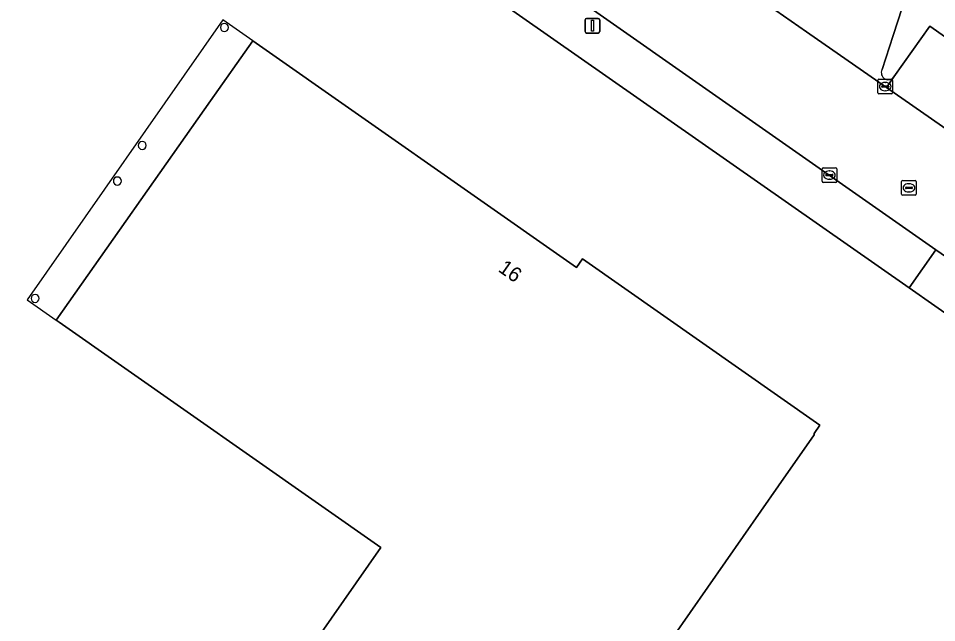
# Model space of a CAD drawing. Extents: x 155018 to 156648, y 383979 to 385733.
# Drawn here: x 155319.4 to 155382, y 385033.8 to 385075 of the extents above; entities that cross this region are included whole.
import ezdxf

# ---------------------------------------------------------------- set-up
doc = ezdxf.new("R2010")
doc.units = 0
for name, color, linetype in [('IMGEO_Erf', 7, 'Continuous'), ('IMGEO_Kolk', 7, 'Continuous'), ('IMGEO_Lichtmast', 7, 'Continuous'), ('IMGEO_Pand', 7, 'Continuous'), ('IMGEO_Pand_nummerreeks', 7, 'Continuous'), ('IMGEO_Pand_overbouw', 7, 'Continuous'), ('IMGEO_Parkeervlak_open', 7, 'Continuous'), ('IMGEO_Rijbaan_lokaal_gesloten', 7, 'Continuous'), ('IMGEO_Rijbaan_lokaal_open', 7, 'Continuous'), ('IMGEO_Rioolput', 7, 'Continuous'), ('IMGEO_Voetpad_open', 7, 'Continuous')]:
    doc.layers.add(name, color=color, linetype=linetype)

msp = doc.modelspace()

# ---------------------------------------------------------------- linework, layer by layer
at = {"layer": 'IMGEO_Erf'}
for points in [[(155421.752, 385027.617), (155394.996, 385046.278), (155391.028, 385049.046), (155385.591, 385052.838), (155385.399, 385052.961), (155380.151, 385056.63), (155341.349, 385083.758), (155335.658, 385087.641), (155324.962, 385095.154), (155317.041, 385100.717), (155292.001, 385118.303), (155289.287, 385120.198), (155288.53, 385120.608), (155288.137, 385120.826), (155288.024, 385120.665), (155281.331, 385125.336), (155281.524, 385125.635), (155276.133, 385129.546), (155243.348, 385152.362), (155212.561, 385173.841)], [(155270.838, 385149.329), (155279.446, 385143.26), (155284.562, 385139.653), (155317.347, 385116.697), (155318.531, 385115.868), (155319.238, 385115.369), (155319.464, 385115.209), (155319.575, 385115.362), (155326.192, 385110.553), (155330.684, 385107.602), (155331.41, 385107.093), (155337.343, 385102.951), (155357.012, 385089.192), (155362.767, 385085.177), (155368.936, 385080.858), (155374.497, 385076.979), (155374.69, 385076.843), (155377.552, 385080.911), (155381.071, 385078.436), (155379.97, 385076.651), (155379.055, 385073.827), (155378.305, 385071.512)], [(155379.115, 385071.004), (155381.551, 385074.471), (155397.68, 385063.161), (155395.287, 385059.711)]]:
    msp.add_lwpolyline(points, dxfattribs=at)
msp.add_lwpolyline([(155322.196, 385054.303), (155322.005, 385054.438), (155332.526, 385069.365), (155335.397, 385073.458), (155357.469, 385058.02), (155357.874, 385058.606), (155374.05, 385047.285), (155373.683, 385046.71), (155373.668, 385046.605), (155371.251, 385043.142), (155360.4, 385027.592), (155346.073, 385007.129), (155329.835, 385018.475), (155344.138, 385038.945)], close=True, dxfattribs=at)
for centre, radius, start, end in [((155333.466, 385074.372), 0.275, 90, 270), ((155333.466, 385074.372), 0.275, 270, 90), ((155378.732, 385071.292), 0.481, 152.72067, 240.84202), ((155378.732, 385071.286), 0.475, 240.50558, 323.64588), ((155327.862, 385066.333), 0.275, 90, 270), ((155327.862, 385066.333), 0.275, 270, 90), ((155326.17, 385063.909), 0.275, 90, 270), ((155326.17, 385063.909), 0.275, 270, 90), ((155320.563, 385055.911), 0.275, 90, 270), ((155320.563, 385055.911), 0.275, 270, 90)]:
    msp.add_arc(centre, radius, start, end, dxfattribs=at)
at = {"layer": 'IMGEO_Kolk'}
for p, q in [((155378.017, 385069.92), (155378.017, 385070.772)), ((155378.092, 385070.846), (155378.944, 385070.846)), ((155379.018, 385070.772), (155379.018, 385069.92)), ((155378.276, 385070.34), (155378.276, 385070.352)), ((155378.714, 385070.303), (155378.316, 385070.303)), ((155378.319, 385070.389), (155378.717, 385070.389)), ((155378.505, 385070.626), (155378.53, 385070.626)), ((155378.76, 385070.352), (155378.76, 385070.34)), ((155378.944, 385069.846), (155378.092, 385069.846)), ((155378.528, 385070.066), (155378.503, 385070.066)), ((155374.21, 385063.892), (155374.21, 385064.744)), ((155374.285, 385064.818), (155375.137, 385064.818)), ((155374.698, 385064.598), (155374.723, 385064.598)), ((155375.211, 385064.744), (155375.211, 385063.892)), ((155375.137, 385063.818), (155374.285, 385063.818)), ((155374.469, 385064.312), (155374.469, 385064.324)), ((155374.907, 385064.275), (155374.509, 385064.275)), ((155374.512, 385064.361), (155374.91, 385064.361)), ((155374.721, 385064.038), (155374.696, 385064.038)), ((155374.953, 385064.324), (155374.953, 385064.312))]:
    msp.add_line(p, q, dxfattribs=at)
for points in [[(155378.017, 385069.92), (155378.017, 385070.772)], [(155378.092, 385070.846), (155378.944, 385070.846)], [(155379.018, 385070.772), (155379.018, 385069.92)], [(155378.944, 385069.846), (155378.092, 385069.846)], [(155374.21, 385063.892), (155374.21, 385064.744)], [(155374.285, 385064.818), (155375.137, 385064.818)], [(155375.211, 385064.744), (155375.211, 385063.892)], [(155375.137, 385063.818), (155374.285, 385063.818)]]:
    msp.add_lwpolyline(points, dxfattribs=at)
for centre, radius, start, end in [((155378.094, 385070.77), 0.0765, 91.55205, 178.44795), ((155378.094, 385070.77), 0.0765, 91.55205, 178.44795), ((155378.942, 385070.77), 0.0765, 1.55205, 88.44795), ((155378.942, 385070.77), 0.0765, 1.55205, 88.44795), ((155378.316, 385070.349), 0.0403, 85.87752, 175.75265), ((155378.313, 385070.339), 0.0366, 178.93798, 274.71019), ((155378.717, 385070.346), 0.043, 264.86636, 352.45326), ((155378.721, 385070.351), 0.0386, 1.73085, 96.63898), ((155378.094, 385069.922), 0.0765, 181.55205, 268.44795), ((155378.094, 385069.922), 0.0765, 181.55205, 268.44795), ((155378.942, 385069.922), 0.0765, 271.55205, 358.44795), ((155378.942, 385069.922), 0.0765, 271.55205, 358.44795), ((155374.287, 385064.742), 0.0765, 91.55205, 178.44795), ((155374.287, 385064.742), 0.0765, 91.55205, 178.44795), ((155375.135, 385064.742), 0.0765, 1.55205, 88.44795), ((155375.135, 385064.742), 0.0765, 1.55205, 88.44795), ((155374.287, 385063.894), 0.0765, 181.55205, 268.44795), ((155374.287, 385063.894), 0.0765, 181.55205, 268.44795), ((155374.509, 385064.321), 0.0403, 85.87752, 175.75265), ((155374.506, 385064.311), 0.0366, 178.93798, 274.71019), ((155374.91, 385064.318), 0.043, 264.86636, 352.45326), ((155374.914, 385064.323), 0.0386, 1.73085, 96.63898), ((155375.135, 385063.894), 0.0765, 271.55205, 358.44795), ((155375.135, 385063.894), 0.0765, 271.55205, 358.44795)]:
    msp.add_arc(centre, radius, start, end, dxfattribs=at)
for centre, major_axis, ratio, start_param, end_param in [((155378.504, 385070.346), (-0.387, 0.002), 0.722429, 4.712389, 7.853982), ((155378.529, 385070.346), (-0.39, 0.002), 0.717154, 1.570796, 4.712389), ((155374.697, 385064.318), (-0.387, 0.002), 0.722429, 4.712389, 7.853982), ((155374.722, 385064.318), (-0.39, 0.002), 0.717154, 1.570796, 4.712389)]:
    msp.add_ellipse(centre, major_axis=major_axis, ratio=ratio, start_param=start_param, end_param=end_param, dxfattribs=at)
at = {"layer": 'IMGEO_Lichtmast'}
for p, q in [((155358.063, 385074.095), (155358.063, 385074.895)), ((155358.063, 385074.895), (155358.063, 385074.095)), ((155358.163, 385074.995), (155358.953, 385074.995)), ((155358.953, 385074.995), (155358.163, 385074.995)), ((155359.053, 385074.895), (155359.053, 385074.095)), ((155359.053, 385074.095), (155359.053, 385074.895)), ((155358.953, 385073.995), (155358.163, 385073.995)), ((155358.163, 385073.995), (155358.953, 385073.995))]:
    msp.add_line(p, q, dxfattribs=at)
msp.add_lwpolyline([(155358.483, 385074.87), (155358.633, 385074.87), (155358.633, 385074.12), (155358.483, 385074.12), (155358.483, 385074.87)], dxfattribs=at)
for centre, start, end in [((155358.163, 385074.895), 90, 180), ((155358.163, 385074.895), 90, 180), ((155358.953, 385074.895), 0, 90), ((155358.953, 385074.895), 360, 90), ((155358.163, 385074.095), 180, 270), ((155358.163, 385074.095), 180, 270), ((155358.953, 385074.095), 270, 0), ((155358.953, 385074.095), 270, 0)]:
    msp.add_arc(centre, 0.1, start, end, dxfattribs=at)
at = {"layer": 'IMGEO_Pand'}
msp.add_lwpolyline([(155360.4, 385027.592), (155371.251, 385043.142), (155373.668, 385046.605), (155373.683, 385046.71), (155374.05, 385047.285), (155357.874, 385058.606), (155357.469, 385058.02), (155335.397, 385073.458), (155332.526, 385069.365), (155322.005, 385054.438), (155322.196, 385054.303), (155344.138, 385038.945), (155329.835, 385018.475), (155346.073, 385007.129)], close=True, dxfattribs=at)
for centre, start, end in [((155333.466, 385074.372), 90, 270), ((155333.466, 385074.372), 270, 90), ((155327.862, 385066.333), 90, 270), ((155327.862, 385066.333), 270, 90), ((155326.17, 385063.909), 90, 270), ((155326.17, 385063.909), 270, 90), ((155320.563, 385055.911), 90, 270), ((155320.563, 385055.911), 270, 90)]:
    msp.add_arc(centre, 0.275, start, end, dxfattribs=at)
at = {"layer": 'IMGEO_Pand_overbouw'}
msp.add_lwpolyline([(155333.363, 385074.901), (155320.027, 385055.822), (155322.005, 385054.438), (155332.526, 385069.365), (155335.397, 385073.458)], close=True, dxfattribs=at)
at = {"layer": 'IMGEO_Parkeervlak_open'}
msp.add_lwpolyline([(155395.287, 385059.711), (155397.68, 385063.161), (155381.551, 385074.471), (155379.115, 385071.004), (155378.611, 385070.279), (155414.442, 385045.348), (155414.644, 385045.638), (155414.382, 385045.812)], dxfattribs=at)
at = {"layer": 'IMGEO_Rijbaan_lokaal_gesloten'}
for points in [[(155254.18, 385148.516), (155259.887, 385144.522), (155262.142, 385142.929), (155267.693, 385139.068), (155276.485, 385133.016), (155284.974, 385127.104), (155291.112, 385122.808), (155293.027, 385121.5), (155293.867, 385120.844), (155318.912, 385103.338), (155326.847, 385097.791), (155337.534, 385090.321), (155343.17, 385086.381), (155381.966, 385059.233), (155386.945, 385055.783), (155387.447, 385055.409), (155392.859, 385051.629), (155396.824, 385048.861), (155422.076, 385031.226)], [(155426.083, 385037.127), (155420.135, 385041.295), (155419.861, 385041.577), (155414.442, 385045.348), (155378.611, 385070.279), (155373.162, 385074.071), (155371.069, 385075.541), (155365.015, 385079.792), (155362.624, 385081.432), (155361.07, 385082.554), (155355.211, 385086.676), (155344.839, 385093.91), (155335.606, 385100.394), (155329.745, 385104.51), (155329.668, 385104.564), (155324.528, 385108.168), (155317.594, 385113.031), (155316.901, 385113.517), (155315.703, 385114.356), (155269.207, 385146.937), (155267.255, 385148.305)]]:
    msp.add_lwpolyline(points, dxfattribs=at)
at = {"layer": 'IMGEO_Rijbaan_lokaal_open'}
for points in [[(155379.055, 385073.827), (155379.97, 385076.651), (155381.071, 385078.436), (155377.552, 385080.911), (155374.69, 385076.843), (155374.635, 385076.765), (155374.349, 385076.359), (155372.1, 385075.71)], [(155371.346, 385075.878), (155371.069, 385075.541), (155373.162, 385074.071), (155378.611, 385070.279), (155379.115, 385071.004)], [(155378.305, 385071.512), (155379.055, 385073.827)]]:
    msp.add_lwpolyline(points, dxfattribs=at)
msp.add_lwpolyline([(155381.966, 385059.233), (155380.151, 385056.63), (155385.399, 385052.961), (155385.591, 385052.838), (155387.447, 385055.409), (155386.945, 385055.783)], close=True, dxfattribs=at)
for centre, radius, start, end in [((155378.732, 385071.292), 0.481, 152.72067, 240.84202), ((155378.732, 385071.286), 0.475, 240.50558, 323.64588)]:
    msp.add_arc(centre, radius, start, end, dxfattribs=at)
at = {"layer": 'IMGEO_Rioolput'}
for p, q in [((155379.637, 385063.018), (155379.637, 385063.87)), ((155379.712, 385063.944), (155380.564, 385063.944)), ((155380.638, 385063.87), (155380.638, 385063.018)), ((155379.896, 385063.438), (155379.896, 385063.45)), ((155380.334, 385063.401), (155379.936, 385063.401)), ((155379.939, 385063.487), (155380.337, 385063.487)), ((155380.125, 385063.724), (155380.15, 385063.724)), ((155380.38, 385063.45), (155380.38, 385063.438)), ((155380.564, 385062.944), (155379.712, 385062.944)), ((155380.148, 385063.164), (155380.123, 385063.164))]:
    msp.add_line(p, q, dxfattribs=at)
for points in [[(155379.637, 385063.018), (155379.637, 385063.87)], [(155379.712, 385063.944), (155380.564, 385063.944)], [(155380.638, 385063.87), (155380.638, 385063.018)], [(155380.564, 385062.944), (155379.712, 385062.944)]]:
    msp.add_lwpolyline(points, dxfattribs=at)
for centre, radius, start, end in [((155379.714, 385063.868), 0.0765, 91.55205, 178.44795), ((155379.714, 385063.868), 0.0765, 91.55205, 178.44795), ((155380.562, 385063.868), 0.0765, 1.55205, 88.44795), ((155380.562, 385063.868), 0.0765, 1.55205, 88.44795), ((155379.936, 385063.447), 0.0403, 85.87752, 175.75265), ((155379.933, 385063.437), 0.0366, 178.93798, 274.71019), ((155380.337, 385063.444), 0.043, 264.86636, 352.45326), ((155380.341, 385063.449), 0.0386, 1.73085, 96.63898), ((155379.714, 385063.02), 0.0765, 181.55205, 268.44795), ((155379.714, 385063.02), 0.0765, 181.55205, 268.44795), ((155380.562, 385063.02), 0.0765, 271.55205, 358.44795), ((155380.562, 385063.02), 0.0765, 271.55205, 358.44795)]:
    msp.add_arc(centre, radius, start, end, dxfattribs=at)
for centre, major_axis, ratio, start_param, end_param in [((155380.124, 385063.444), (-0.387, 0.002), 0.722429, 4.712389, 7.853982), ((155380.149, 385063.444), (-0.39, 0.002), 0.717154, 1.570796, 4.712389)]:
    msp.add_ellipse(centre, major_axis=major_axis, ratio=ratio, start_param=start_param, end_param=end_param, dxfattribs=at)
at = {"layer": 'IMGEO_Voetpad_open'}
msp.add_lwpolyline([(155380.151, 385056.63), (155381.966, 385059.233), (155343.17, 385086.381), (155341.349, 385083.758)], close=True, dxfattribs=at)

# ---------------------------------------------------------------- texts
at = {"layer": 'IMGEO_Pand_nummerreeks'}
msp.add_text('16', height=1, rotation=325.02959, dxfattribs=at).set_placement((155352.07, 385057.794))

doc.saveas('drawing.dxf')
